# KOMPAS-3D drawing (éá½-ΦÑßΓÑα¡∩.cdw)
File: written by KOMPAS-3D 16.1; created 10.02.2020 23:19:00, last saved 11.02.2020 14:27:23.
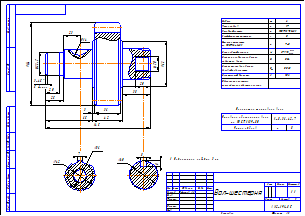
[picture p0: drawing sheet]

Sheet 1: A3, landscape

Title block, sheet 1: name: Вал-шестерня; scale: 1:1; sheets: 1; organisation: АХ2-191-ДБ; sheet format: A3; stored path: D:\ЗАДАЧИ\Начертательная геометрия и инженерная графика. 4 задания Р\Задание 4\Вал-шестерня.cdw; drawn by: Ефремов А.Л.

Views: Вид 4, Вид 7, Вид 8
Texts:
  Пользователь Windows
  Ячейка таблицы
  Обозначение чертежа
  сопряжённого зубчатого колеса
  Делительный диаметр
  Допуск торцового биения
  базовой поверхности
  Допуск на радиальное биение
  зубчатого венца
  Длина общей нормали
  Степень точности
  по ГОСТ 1643-81
  Коэффициент смещения
  Исходный контур
  Число зубьев
  Модуль
  ГОСТ 13755-81
  Таблица параметров
  Условное обозначение вала
  по ГОСТ 1139-80
  Параметры шлицевого вала
  Неуказанные радиусы 3 мм.
Dimensions and other numbers on the sheet: 102; 0,025; 0,04; 27,998 -0,07 -0,14; 7-C; 0; 17; 6; 8; 33; 40; 20; 38; 145; 3; 5 фасок; 25; 65; 42; 36; 14; 114; 7; 23; 63; 1:1; 1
